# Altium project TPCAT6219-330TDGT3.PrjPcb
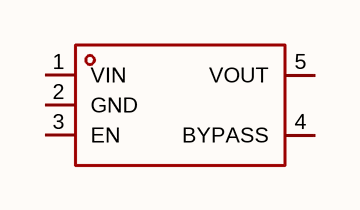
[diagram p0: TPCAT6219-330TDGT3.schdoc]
1 sheet, 1 parts. Net scope: global (net labels, ports and power ports of the same name join across sheets).

## Sheet TPCAT6219-330TDGT3.schdoc
size 127 x 101 mm

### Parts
U?  tpcat6219-330tdgt3  [SOT-23-5_L3.0-W1.7-P0.95-LS2.8-BL]  (value not drawn)

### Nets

Not connected (* = marked no-connect by the designer): U? 1(VIN) 2(GND) 3(EN) 4(BYPASS) 5(VOUT)

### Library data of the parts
U? = tpcat6219-330tdgt3: 输出极性:正极;工作电压:5.5V;输出电压:3.3V;输出电流:500mA;电源纹波抑制比(PSRR):68dB@(1kHz);输出类型:固定;; Manufacturer: TECH PUBLIC(台舟); AddInBom: yes; ModelId: 0a2a1b8f50944f73965918ad6e5fe167; ModelName: SOT-23-5_L2.9-W1.6-H1.1-LS2.8-P0.95; ModelTransform: 118.60433,114.173,0,90,0,0,0.0005,0.0005,0; Output Configuration: 正极; Voltage - Supply: 5.5V; Output Voltage: 3.3V; Output Current: 500mA; Voltage Dropout: 85mV@(100mA); standby current: 10uA; Output Type: 固定; Number of Outputs: 1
